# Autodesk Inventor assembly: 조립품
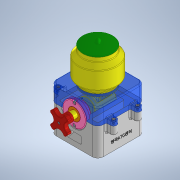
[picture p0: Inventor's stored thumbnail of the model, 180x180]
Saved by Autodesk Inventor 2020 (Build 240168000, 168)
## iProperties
Created: 2022-03
Part Number: 조립품
Document SubType Name: Assembly
Designer: Administrator
Author: Administrator
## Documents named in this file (11)
- C:\Users\Administrator\Desktop\720306V1018\조립품.iam
- C:\Users\Administrator\Desktop\720306V1018\본체.ipt
- C:\Users\Administrator\Desktop\720306V1018\본체커버.ipt
- C:\Users\Administrator\Desktop\720306V1018\용기.ipt
- C:\Users\Administrator\Desktop\720306V1018\용기캡.ipt
- C:\Users\Administrator\Desktop\720306V1018\핸들축.ipt
- C:\Users\Administrator\Desktop\720306V1018\앞커버.ipt
- C:\Users\Administrator\Desktop\720306V1018\베어링 부시.ipt
- C:\Users\Administrator\Desktop\720306V1018\볼트 M4x12.ipt
- C:\Users\Administrator\Desktop\720306V1018\핸들.ipt
- C:\Users\Administrator\Desktop\720306V1018\볼트 M3x12.ipt
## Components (2 placed, 2 different names)
1. 핸들축:1
2. 핸들:1
